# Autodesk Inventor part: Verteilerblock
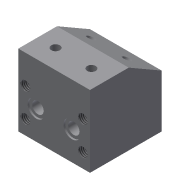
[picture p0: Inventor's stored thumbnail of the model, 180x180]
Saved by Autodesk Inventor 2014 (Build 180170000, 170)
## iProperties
Company: VDW-Nachwuchsstiftung
Created: 2014-04
Part Number: Verteilerblock
Material: Generisch
Document SubType Name: Modeling
Designer: e_dammj
Density: 1 g/cm^3
Appearance: Vorgabe
Author: e_dammj
Title: Verteilerblock
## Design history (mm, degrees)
sketch "Skizze1"
  geometry: L1 (-25, -25)-(25, -25); L2 (25, -25)-(25, 25); L3 (25, 25)-(-25, 25); L4 (-25, 25)-(-25, -25); L5 (-25, -25)-(25, 25); L6 (25, -25)-(-25, 25); 1 further point
  constraints: 12 end point, 2 midpoint, 2 parallel, 1 horizontal, 1 perpendicular
  dimensions: "d0" = 50 distance of L3.end L2.end; "d1" = 50 distance of L2.end L1.end
extrude "Grundkörper" new body sketch "Skizze1" distance "d2" = 50; taper "d3" = 0 deg
sketch "Skizze2"
  geometry: L1 (50, 50)-(50, 0) reference; L2 (0, 50)-(50, 50) reference; L3 (27, 50)-(50, 36.721); 1 further point
  constraints: 2 end point, 2 point on line
  dimensions: "d4" = 30 deg angle of L2 L3; "d5" = 27 distance of L2.start L3.start
extrude "Schräge Fläche" cut sketch "Skizze2" stored distance "d6" = 50; taper "d7" = 0 deg
sketch "Skizze3"
  geometry: L1 (-25, -25)-(25, -25) reference; L2 (-25, 25)-(-25, -25) reference; L3 (0, 26.943)-(0, -27.881) reference; 5 further points
  constraints: 2 end point, 2 symmetric about line, 1 parallel, 1 vertical, 1 vertical alignment
  dimensions: "d10" = 20 distance of point (-20, -15) point (-20, 5); "d11" = 10 distance from line of L1 point (-20, -15); "d13" = 40 diameter of point (-20, 5) L3
hole "Gewindebohrung M8" sketch "Skizze3" at (-20, -15), (-20, 5), (20, 5), (20, -15) diameter "d14" = 6.647; stored, may be unused: countersink angle "d18" = 90 deg, drill point angle "d20" = 118 deg; dims "d15" = 12, "d16" = 4, "d17" = 2, "d19" = 16
sketch "Skizze4"
  geometry: L1 (-25, -25)-(25, -25) reference; L2 (-25, 25)-(-25, -25) reference; L3 (0, 28.583)-(0, -27.881) reference; 3 further points
  constraints: 2 end point, 1 parallel, 1 symmetric about line, 1 vertical
  dimensions: "d21" = 25 diameter of point (-12.5, -5) L3; "d22" = 20 distance from line of L1 point (-12.5, -5)
hole "Senkbohrung D12" sketch "Skizze4" at (-12.5, -5), (12.5, -5) diameter "d23" = 8; stored, may be unused: countersink angle "d27" = 90 deg, drill point angle "d29" = 118 deg; dims "d24" = 12, "d25" = 12, "d26" = 1.2, "d28" = 33
sketch "Skizze5"
  geometry: L1 (50, 0)-(0, 0) reference; L2 (50, 0)-(50, 27) reference; L3 (25, -2.197)-(25, 53.329) reference; 3 further points
  constraints: 2 end point, 1 parallel, 1 symmetric about line, 1 vertical
  dimensions: "d30" = 25 diameter of point (12.5, 13.5) L3; "d31" = 13.5 distance from line of L1 point (12.5, 13.5)
hole "Bohrung D6" sketch "Skizze5" at (12.5, 13.5), (37.5, 13.5) diameter "d32" = 6; stored, may be unused: countersink angle "d36" = 90 deg, drill point angle "d38" = 118 deg; dims "d33" = 12, "d34" = 12, "d35" = 1.2, "d37" = 28.25
sketch "Skizze6"
  geometry: L1 (50, 0)-(0, 0) reference; L2 (0, 26.558)-(50, 26.558) reference; L3 (25, -1.609)-(25, 29.986) reference; 3 further points
  constraints: 2 end point, 1 perpendicular, 1 symmetric about line, 1 vertical
  dimensions: "d39" = 25 diameter of point (12.5, 13.279) L3; "d40" = 13.279 distance from line of L1 point (12.5, 13.279)
hole "Schräge Bohrung D6" sketch "Skizze6" at (12.5, 13.279), (37.5, 13.279) diameter "d41" = 6; stored, may be unused: countersink angle "d45" = 90 deg, drill point angle "d47" = 118 deg; dims "d42" = 12, "d43" = 12, "d44" = 1.2, "d46" = 28.25
node "Volumenkörper1"
